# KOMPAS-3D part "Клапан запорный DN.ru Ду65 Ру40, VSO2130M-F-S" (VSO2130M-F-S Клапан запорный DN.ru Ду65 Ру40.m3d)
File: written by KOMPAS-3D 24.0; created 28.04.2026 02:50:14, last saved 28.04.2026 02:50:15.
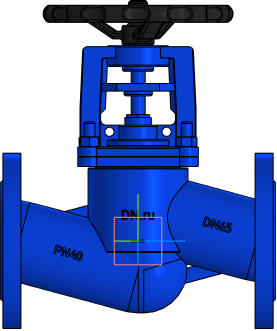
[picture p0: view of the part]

Document properties: Автор: DN.ru; Полное имя файла: C:\Работа\ГОТОВЫЕ ИСХОДНИКИ\VSO2130M-F-S Клапан запорный сильфонный DN.ru Ду15-100 Ру40\DN65\VSO2130M-F-S Клапан запорный DN.ru Ду65 Ру40.m3d

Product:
- Part/product: Клапан запорный DN.ru Ду65 Ру40  | designation VSO2130M-F-S
    Масса: 17
    Раздел спецификации: Прочие изделия
    Примечание: D090-01976

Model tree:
1. Операция без истории:1

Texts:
  VSO2130M-F-S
